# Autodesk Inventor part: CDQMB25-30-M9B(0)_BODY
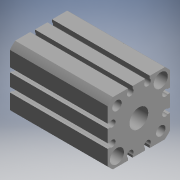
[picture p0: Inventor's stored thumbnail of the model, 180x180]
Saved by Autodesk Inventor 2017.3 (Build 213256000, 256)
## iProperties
Part Number: CDQMB25-30-M9B(0)_BODY
Material: Generic
Catalog Web Link: www.cadenas.de
Description: CQM_BODY-Compact Cylinder Guide Rod Type
Vendor: SMC
Document SubType Name: Modeling
Designer: partserver
Manufacturer: SMC
Mass: 63.9231 g
Surface Area: 256.821 cm^2
Volume: 63.9231 cm^3
Density: 1 g/cm^3
Appearance: PSOLRGB-192-192-192
Category: PARTsolutions
Company: SMC
Title: CDQMB25-30-M9B_BODY
Author: Cadenas PARTsolutions
Comments: Compact Cylinder Guide Rod Type
PSOL_IDENT_0: {$CADENAS_DATA\23d-libs\smc_jp\actuator\compact_cylinder\cqm\parts\cqm_body.prj},229 {VTYP=3D},{NB=C
PSOL_IDENT_1: DQMB25-30-M9B(0)_BODY},{LINA=CDQMB25-30-M9B_BODY},{NN=CQM_BODY},{DATE=09.12.2020 02:52:29},{GEOMDATE=
PSOL_IDENT_2: 26.03.2020 06:55:43},{VERSION=},{LINEID=40},{WBVAR=MAGNET,THREAD1,AUTOSWITCH,STROKE,THREAD2},{WBNUME
PSOL_IDENT_3: RIC=STROKE}  {NB=CDQMB25-30-M9B(0)_BODY},{LINA=CDQMB25-30-M9B_BODY},{KT=DUMMY},{BORE=25},{DX=3.000},
PSOL_IDENT_4: {MAGNET=D},{MOUNT=(B) Through-hole/Both ends tapped (Standard)},{MOUNTX=B},{THREAD1=},{THREAD1X='','
PSOL_IDENT_5: (-) M thread'},{AUTOSWITCH=-M9B},{AUTOSWITCHX='','(-) Without autoswitch','-M9NV','M9NV', '-M9PV', '
PSOL_IDENT_6: M9PV', '-M9BV', 'M9BV','-M9NWV', 'M9NWV', '-M9PWV', 'M9PWV', '-M9BWV', 'M9BWV', '-A96V', 'A96V', '-A
PSOL_IDENT_7: 93V', 'A93V', '-A90V', 'A90V', '-M9N', 'M9N', '-M9P', 'M9P', '-M9B', 'M9B', '-M9NW', 'M9NW', '-M9PW'
PSOL_IDENT_8: , 'M9PW', '-M9BW', 'M9BW', '-A96', 'A96','-A93', 'A93', '-A90', 'A90', '-M9NAV', 'M9NAV', '-M9PAV', '
PSOL_IDENT_9: M9PAV', '-M9BAV', 'M9BAV', '-M9NA', 'M9NA', '-M9PA','M9PA', '-M9BA', 'M9BA'},{STROKE=30},{STROKEX=[1
PSOL_IDENT_10: :50/1]},{STROKEX2=30},{SWITCHX=2},{SMAX=50},{THREAD2=0},{ORDER=CDQMB25-30-M9B},{A=45.5},{A1=35.5},{A
PSOL_IDENT_11: 2=45.5},{B=32.5},{B1=22.5},{B2=32.5},{EA=40},{EB=38},{EC=0.0},{F=5.5},{F1=5.5},{HA=M5x0.8},{OA=M6x1.
PSOL_IDENT_12: 0},{OARA=6},{OARP=1.00},{OAX=1},{HB=5 +0.2/0},{HBX=5},{IA=52},{IB=50.5},{J=0.0},{KA=22 +0.1/-0.1},{K
PSOL_IDENT_13: AX=22},{KB=15.6},{L=5.0},{M=28.0},{N=5.4},{OB=9.0},{Q=11.0},{Q1=11.0},{RA=10},{RB=7.0},{T=1.0},{V=30
PSOL_IDENT_14: .0},{W=8},{Z=0},{PP=M5x0.8},{PTN=-},{PTF=-},{PND=5.000},{PD=3},{LC4=6},{P=M5x0.8},{AA=11.0},{AAY=-5.
PSOL_IDENT_15: 5},{AA1=7.0},{AA2=11.0},{AA3=0.0},{AA4=0.0},{AA5=0.0},{BB=9.5},{BBY=5.5},{BB1=5.5},{BB2=9.5},{BB3=0.
PSOL_IDENT_16: 0},{BB4=0.0},{BB5=0.0},{LC1=11.0},{LC2=0.0},{LC3=12},{LR=6}
NB: CDQMB25-30-M9B(0)_BODY
NN: CQM_BODY
NT: Compact Cylinder Guide Rod Type
NBSYN: $ORDER.($THREAD2.)_BODY
LINA: CDQMB25-30-M9B_BODY
CATALOG: SMC (JP
BORE: 25
DX: 3
MAGNET: (D) With magnet
MOUNT: (B) Through-hole/Both ends tapped (Standard)
THREAD1: (-) M thread
AUTOSWITCH: M9B
STROKE: 30
SMAX: 50
THREAD2: on
A: 45.5
A1: 35.5
A2: 45.5
B: 32.5
B1: 22.5
B2: 32.5
EA: 40
EB: 38
EC: 0
F: 5.5
F1: 5.5
HA: M5x0.8
OA: M6x1.0
OARA: 6
OARP: 1
HB: 5 +0.2/0
HBX: 5
IA: 52
IB: 50.5
J: 0
KA: 22 +0.1/-0.1
KAX: 22
KB: 15.6
L: 5
M: 28
N: 5.4
OB: 9
Q: 11
Q1: 11
RA: 10
RB: 7
T: 1
V: 30
W: 8
Z: 0
PP: M5x0.8
PTN: -
PTF: -
PND: 5
PD: 3
LC4: 6
P: M5x0.8
AA: 11
AA1: 7
AA2: 11
AA3: 0
AA4: 0
AA5: 0
BB: 9.5
BB1: 5.5
BB2: 9.5
BB3: 0
BB4: 0
BB5: 0
LC1: 11
LC2: 0
LC3: 12
LR: 6
SUPPLIER: SMC
ARTICLENO: CDQMB25-30-M9B(0)_BODY
BOMINFO: CDQMB25-30-M9B_BODY
CREATOR: CADENAS GmbH
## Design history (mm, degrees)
sketch "Sketch_14"
  geometry: L1 (7, 20)-(7, 18.47); L2 (4, 18.47)-(4, 19.85); L3 (4, 19.85)-(-4, 19.85); L4 (-4, 19.85)-(-4, 18.47); L5 (-7, 18.47)-(-7, 20); L6 (-7, 20)-(-16.613, 20); L7 (-20, 16.613)-(-20, 7); L8 (-20, 7)-(-18.47, 7); L9 (-18.47, 4)-(-19.85, 4); L10 (-19.85, 4)-(-19.85, -4); L11 (-19.85, -4)-(-18.47, -4); L12 (-18.47, -7)-(-20, -7); L13 (-20, -7)-(-20, -16.613); L14 (-16.613, -20)-(-7, -20); L15 (-7, -20)-(-7, -18.47); L16 (-4, -18.47)-(-4, -19.85); L17 (-4, -19.85)-(4, -19.85); L18 (4, -19.85)-(4, -18.47); L19 (7, -18.47)-(7, -20); L20 (7, -20)-(16.613, -20); L21 (20, -16.613)-(20, -7); L22 (20, -7)-(18.47, -7); L23 (18.47, -4)-(19.85, -4); L24 (19.85, -4)-(19.85, 4); L25 (19.85, 4)-(18.47, 4); L26 (18.47, 7)-(20, 7); L27 (20, 7)-(20, 16.613); L28 (16.613, 20)-(7, 20); A1 r 2.1 centre (5.5, 17) between (4, 18.47) and (7, 18.47); A2 r 2.1 centre (-5.5, 17) between (-7, 18.47) and (-4, 18.47); A3 r 26 centre (0, 0) between (-16.613, 20) and (-20, 16.613); A4 r 2.1 centre (-17, 5.5) between (-18.47, 4) and (-18.47, 7); A5 r 2.1 centre (-17, -5.5) between (-18.47, -7) and (-18.47, -4); A6 r 26 centre (0, 0) between (-20, -16.613) and (-16.613, -20); A7 r 2.1 centre (-5.5, -17) between (-4, -18.47) and (-7, -18.47); A8 r 2.1 centre (5.5, -17) between (7, -18.47) and (4, -18.47); A9 r 26 centre (0, 0) between (16.613, -20) and (20, -16.613); A10 r 2.1 centre (17, -5.5) between (18.47, -4) and (18.47, -7); A11 r 2.1 centre (17, 5.5) between (18.47, 7) and (18.47, 4); A12 r 26 centre (0, 0) between (20, 16.613) and (16.613, 20)
  constraints: 56 end point, 24 point on circle, 12 centre point
extrude "Extrusion1" join sketch "Sketch_14" distance "d0" = 62.5; taper "d1" = 0 deg
sketch "Sketch_4"
  geometry: L1 (62.5, -14)-(0, -14); L2 (0, -14)-(0, -9.5); L3 (0, -9.5)-(7, -9.5); L4 (7, -9.5)-(7, -11); L5 (7, -11)-(7.542, -11.541); L6 (7.542, -11.541)-(17, -11.541); L7 (17, -11.541)-(17, -11.3); L8 (17, -11.3)-(45.5, -11.3); L9 (45.5, -11.3)-(45.5, -11.541); L10 (45.5, -11.541)-(54.959, -11.541); L11 (54.959, -11.541)-(55.5, -11); L12 (55.5, -11)-(55.5, -9.5); L13 (55.5, -9.5)-(62.5, -9.5); L14 (62.5, -9.5)-(62.5, -14); L15 (62.5, -14)-(0, -14)
  constraints: 30 end point
revolve "Revolution1" sketch "Sketch_4" stored, may be unused: angle "d2" = 360 deg
thread "Thread1" dims "d3" = 9.4585, "d4" = 0
thread "Thread2" dims "d5" = 9.4585, "d6" = 0
pattern_linear "Rectangular Pattern1" dims "d9" = 39.59798, "d12" = 0
sketch "Sketch_12"
  geometry: L1 (51.25, 14)-(0, 14); L2 (0, 14)-(0, 17); L3 (0, 17)-(51.25, 17); L4 (51.25, 17)-(51.25, 14); L5 (51.25, 14)-(0, 14)
  constraints: 10 end point
revolve "Revolution2" sketch "Sketch_12" stored, may be unused: angle "d13" = 360 deg
pattern_linear "Rectangular Pattern2" dims "d16" = 39.59798, "d19" = 0
sketch "Sketch_5"
  geometry: L1 (51.25, 0)-(0, 0); L2 (0, 0)-(0, 6); L3 (0, 6)-(16.25, 6); L4 (16.25, 6)-(16.25, 12.5); L5 (16.25, 12.5)-(51.25, 12.5); L6 (51.25, 12.5)-(51.25, 0); L7 (51.25, 0)-(0, 0)
  constraints: 14 end point
revolve "Revolution3" sketch "Sketch_5" stored, may be unused: angle "d20" = 360 deg
sketch "Sketch_17"
  geometry: L1 (11, 15.807)-(11, 20); L2 (11, 20)-(13.5, 20); L3 (13.5, 20)-(13.067, 19.567); L4 (13.067, 19.567)-(13.067, 17); L5 (13.067, 17)-(11, 15.807); L6 (11, 15.807)-(11, 20)
  constraints: 12 end point
revolve "Revolution4" sketch "Sketch_17" stored, may be unused: angle "d21" = 360 deg
thread "Thread3" dims "d22" = 2.567, "d23" = 0
sketch "Sketch_18"
  geometry: L1 (57, 15.807)-(57, 20); L2 (57, 20)-(59.5, 20); L3 (59.5, 20)-(59.067, 19.567); L4 (59.067, 19.567)-(59.067, 17); L5 (59.067, 17)-(57, 15.807); L6 (57, 15.807)-(57, 20)
  constraints: 12 end point
revolve "Revolution5" sketch "Sketch_18" stored, may be unused: angle "d24" = 360 deg
thread "Thread4" dims "d25" = 2.567, "d26" = 0
node "BODY_DUMMY_XY"
node "BODY_DUMMY_YZ"
node "BODY_DUMMY_ZX"
node "BODY_DUMMY_X"
node "BODY_DUMMY_Y"
node "BODY_DUMMY_Z"
node "BODY_DUMMY_Center"
node "BODY_ROD_XY"
node "BODY_ROD_YZ"
node "BODY_ROD_ZX"
node "BODY_ROD_X"
node "BODY_ROD_Y"
node "BODY_ROD_Z"
node "BODY_ROD_Center"
node "BODY_SWA_XY"
node "BODY_SWA_YZ"
node "BODY_SWA_ZX"
node "BODY_SWA_X"
node "BODY_SWA_Y"
node "BODY_SWA_Z"
node "BODY_SWA_Center"
node "BODY_SWB_XY"
node "BODY_SWB_YZ"
node "BODY_SWB_ZX"
node "BODY_SWB_X"
node "BODY_SWB_Y"
node "BODY_SWB_Z"
node "BODY_SWB_Center"
node "F_1_XY"
node "F_1_YZ"
node "F_1_ZX"
node "F_1_X"
node "F_1_Y"
node "F_1_Z"
node "F_1_Center"
node "J_XY"
node "J_YZ"
node "J_ZX"
node "J_X"
node "J_Y"
node "J_Z"
node "J_Center"
node "M_1_XY"
node "M_1_YZ"
node "M_1_ZX"
node "M_1_X"
node "M_1_Y"
node "M_1_Z"
node "M_1_Center"
node "M_2_XY"
node "M_2_YZ"
node "M_2_ZX"
node "M_2_X"
node "M_2_Y"
node "M_2_Z"
node "M_2_Center"
node "P_XY"
node "P_YZ"
node "P_ZX"
node "P_X"
node "P_Y"
node "P_Z"
node "P_Center"
node "Z_2_XY"
node "Z_2_YZ"
node "Z_2_ZX"
node "Z_2_X"
node "Z_2_Y"
node "Z_2_Z"
node "Z_2_Center"
body "Solid1"
other parameters: "d27" = 0, "d28" = 0, "d29" = 0, "d30" = 0, "d31" = 0, "d32" = 0
